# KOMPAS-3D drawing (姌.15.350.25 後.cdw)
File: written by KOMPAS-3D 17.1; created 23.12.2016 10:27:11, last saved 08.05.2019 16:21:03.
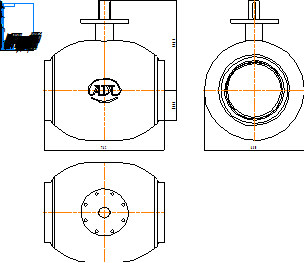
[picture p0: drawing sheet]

Sheet 1: A4, portrait

Title block, sheet 1: name: КШ.15.350.25 сс; material: Внимание! Данный продукт является объектом авторского права ООО «Торговый Дом АДЛ». / Запрещается изменение, копирование, распространение / (в том числе путем копирования на другие сайты и ресурсы в Интернете) / или любое иное использование информации и объектов без предварительного / согласия правообладателя (ООО «Торговый Дом АДЛ»).; sheets: 1; organisation: ООО "Торговый дом АДЛ"; sheet format: A4; stored path: C:\Users\tra\Desktop\2д чертежи\Шаровые краны БИВАЛ\КШ_Бивал_серия_14_15\KOMPAS_2D\КШ.15.350.25 сс.cdw

Views: Вид 1, Проекционный вид 2, Проекционный вид 3
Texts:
  Klimkovich
  ADL
Dimensions and other numbers on the sheet: 762; 564,5; 188,5; 630; 1:1; 1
